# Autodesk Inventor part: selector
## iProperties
Created: 2006-04
Part Number: selector
Document SubType Name: Modeling
Designer: Калинин
Author: Калинин
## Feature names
1. Выдавливание1 [Extrusion]
2. Выдавливание2 [Extrusion]
3. Выдавливание3 [Extrusion]
4. Выдавливание4 [Extrusion]
5. Выдавливание5 [Extrusion]
6. Выдавливание6 [Extrusion]
7. Выдавливание7 [Extrusion]
8. Сопряжение1 [Fillet]
9. Фаска1 [Chamfer]
10. Вращение1 [Revolution]
11. Вращение2 [Revolution]
12. Выдавливание8 [Extrusion]
13. Фаска2 [Chamfer]
14. Вращение3 [Revolution]
15. Фаска3 [Chamfer]
16. Фаска4 [Chamfer]
